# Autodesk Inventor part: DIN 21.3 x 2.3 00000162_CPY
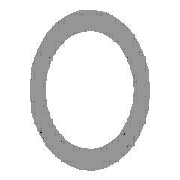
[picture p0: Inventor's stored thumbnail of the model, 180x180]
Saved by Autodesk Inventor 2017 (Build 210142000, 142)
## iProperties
Created: 2017-11
Part Number: DIN 21.3 x 2.3 00000162_CPY
Material: Steel, Mild
Description: Pipe
Document SubType Name: Modeling
Standard: DIN
Designer: iusti
Standard Revision: 2006-07
Standards Organization: DIN
Language: en-US
Size Designation: 21.3 x 2.3
Categories: <MemberInstance><Categories><Category DisplayName="Structural Shapes" InternalName="089c4875-fa83-4c05-b084-43b9cc11f5ed" Mnemonic="GRDR"><CategoryParameter Dis
Stock Number: 21.3 x 2.3
Density: 7.85 g/cm^3
Appearance: Semi-Polished
IsCustomPart: 1
G_L: 500.000 mm
G_W: 21.300 mm
G_H: 21.300 mm
_CCFamilyMember: 1
_CCFamilyDisplayName: DIN EN 10210-2 - Pipe
_FrameMemberDoc: Frame Member File
_Version: 15.0.0
_GetPNFromCC: 1
Author: iusti
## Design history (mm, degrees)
node "Start plane"
node "End plane"
sketch "Sketch"
  geometry: C1 r 8.35 at (0, 0); C2 r 10.65 at (0, 0); 2 further points
  constraints: 3 coincident, 2 centre point
  dimensions: "d0" = 21.3 diameter of C2 (= G_H); "d1" = 2.3 radial gap between concentric circles of C2 C1 (= G_T)
extrude "Body" new body sketch "Sketch" stored distance "d2" = 500 (= G_L); taper "d3" = 0 deg
node "Driven Length"
  sketch "Sketch3"
    geometry: L1 (0, 0)-(10, 0) reference
    constraints: 2 end point, 1 horizontal
  workplane "Work Plane3"
  sketch "Sketch4"
    geometry: L1 (-2, 0)-(12, 0) reference; L2 (-2, 500)-(12, 500) reference
    dimensions: "d7" = 500 distance between parallel lines of L1 L2 (derived)
body "Solid1"
other parameters: "G_H" = 21.3 [user parameter; used in 1 equation term], "G_T" = 2.3 [user parameter; used in 1 equation term], "G_L" = 500 (= d7) [user parameter; used in 1 equation term], "G_OFFSET_START" = 0 [user parameter; used in 1 equation term], "G_OFFSET_END" = 0 [user parameter; used in 1 equation term], "d4" = 0 (computed from G_OFFSET_START), "d6" = 90 deg
